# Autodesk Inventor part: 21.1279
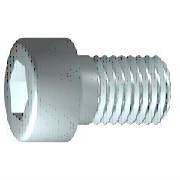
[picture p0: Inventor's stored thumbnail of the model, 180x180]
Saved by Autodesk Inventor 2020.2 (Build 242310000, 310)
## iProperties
Created: 2006-02
Part Number: 21.1279
Material: Steel, Mild
Description: M5X10 SHCS
Document SubType Name: Modeling
Standard: DIN 7984
Designer: Andy Moles
Standards Organization: DIN
Language: en-US
Size Designation: M5 x 12
Categories: <MemberInstance><Categories><Category DisplayName="Fasteners" InternalName="e4da775c-781d-43d5-af7c-5136215cf5a6" Mnemonic="FSTN"><Category DisplayName="Bolts"
Density: 7.85 g/cm^3
Vendor: S
Mass: 2.8864 g
Surface Area: 3.83541 cm^2
Volume: 0.367694 cm^3
Appearance: Zinc
Author: Andy Moles
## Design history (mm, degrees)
sketch "Sketch1"
  geometry: L1 (0.2, 0)-(10, 0); L2 (10, 0)-(10, 2.5); L3 (10, 2.5)-(0.4, 2.5); L4 (0, 2.5)-(0, 4.25); L5 (0, 4.25)-(-3.5, 4.25); L6 (-3.5, 4.25)-(-3.5, 1.732); L7 (-3.5, 1.732)-(-0.8, 1.732); L8 (-0.8, 1.732)-(0.2, 0); L9 (-6.2, 0)-(12.7, 0) reference; L10 (0, -0.85)-(0, 5.1) reference; L11 (0.4, 2.5)-(0, 2.5); L12 (0.4, 2.5)-(0, 2.5)
  constraints: 20 end point, 5 parallel, 3 perpendicular, 2 collinear, 1 horizontal, 1 point on line
  dimensions: "d1" = 9.6 distance from line of L3.end L2 (= GEL); "d3" = 3.5 distance between parallel lines of L6 L4 (= KOH); "d4" = 2.7 distance of L6.end L7.end (= INTI); "d5" = 60 deg angle of L8 L1; "d6" = 5 diameter of L3 L1 (= GD); "d8" = 3.4641 diameter of L7 L1 (= 1.1547 x SW); "d9" = 8.5 diameter of L5 L1 (= KOD); "d26" = 10 distance between parallel lines of L10 L2
revolve "Body" sketch "Sketch1" stored, may be unused: angle "d10" = 90 deg
sketch "Sketch2"
  geometry: L1 (0, -5.95)-(0, 5.95) reference; L2 (-5.95, 0)-(5.95, 0) reference; L3 (1.732, 0)-(0.866, -1.5); L4 (0.866, -1.5)-(-0.866, -1.5); L5 (-0.866, -1.5)-(-1.732, 0); L6 (-1.732, 0)-(-0.866, 1.5); L7 (-0.866, 1.5)-(0.866, 1.5); L8 (0.866, 1.5)-(1.732, 0); 2 further points
  constraints: 12 end point, 1 coincident, 1 horizontal alignment, 1 point on line, 12 other
extrude "Slot" join sketch "Sketch2" stored distance "d11" = 10; taper "d12" = 0 deg
workplane "Work Plane1"
body "Solid1"
fillet "Fillet1" dims "d17" = 0.5 (= RR)
feature "Thread" dims "d13" = 16, "d14" = 0
chamfer "Chamfer1" distance "d15" = 0.49076 (= -0.5 x SPD + 0.5 x GD); stored, may be unused: second distance "d16" = 0.49076 (= GUL), angle "d27" = 45 deg
other parameters: "GD" = 5 (= NND) [user parameter; used in 2 equation terms], "NLG" = 12 [user parameter], "GEL" = 9.6 [user parameter; used in 1 equation term], "KOD" = 8.5 [user parameter; used in 1 equation term], "KOH" = 3.5 [user parameter; used in 1 equation term], "INTI" = 2.7 [user parameter; used in 1 equation term], "GAL" = 0.49076 (= 0.61345 x PTC) [user parameter], "GUL" = 0.49076 (= 0.61345 x PTC) [user parameter; used in 1 equation term], "BDM" = 5 (= NND) [user parameter], "SW" = 3 [user parameter; used in 2 equation terms], "RR" = 0.5 [user parameter; used in 1 equation term], "SPD" = 4.01848 (= NND - 1.2269 x PTC) [user parameter; used in 1 equation term], "d19" = 0, "d28" = 0, "d29" = 0, "TOA" = 30 deg [user parameter], "GD1" = 4.01848 (= THREADDIA - 1.2269 x PTC) [user parameter], "THREADDIA" = 5 [user parameter; used in 1 equation term], "FAWI" = 45 deg [user parameter], "ANG" = 120 deg [user parameter], "TPU" = 12.5 (computed from PTC) [user parameter], "PTC" = 0.8 [user parameter; used in 5 equation terms], "NND" = 5 [user parameter; used in 3 equation terms], "E0" = 3.465 (= 1.155 x SW) [user parameter]
